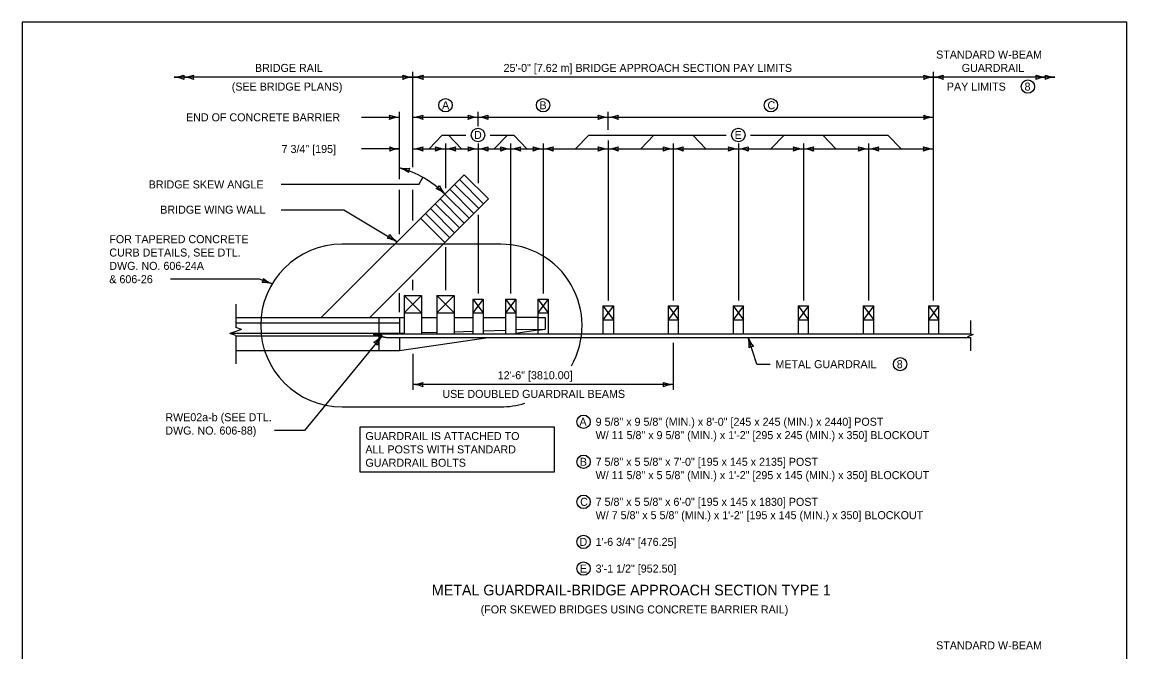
# Model space of a CAD drawing. Extents: x 49991.4 to 50021, y 49987.6 to 50011.4.
# Drawn here: x 50000.34 to 50008.61, y 50006.54 to 50011.26 of the extents above; entities that cross this region are included whole.
import ezdxf

# ---------------------------------------------------------------- set-up
doc = ezdxf.new("R2010")
doc.units = 0
for name, color, linetype in [('Level 1', 7, 'Continuous'), ('Level 2', 7, 'Continuous'), ('Level 3', 7, 'Continuous'), ('Level 4', 7, 'Continuous'), ('Level 6', 7, 'Continuous')]:
    doc.layers.add(name, color=color, linetype=linetype)

msp = doc.modelspace()

# ---------------------------------------------------------------- linework, layer by layer
at = {"layer": 'Level 1'}
for p, q in [((50002.5778, 50009.048), (50003.649, 50010.1194)), ((50003.758, 50009.8652), (50003.5764, 50010.0467)), ((50003.7943, 50009.9015), (50003.6127, 50010.0831)), ((50003.8306, 50009.9378), (50003.649, 50010.1194)), ((50003.6853, 50009.7925), (50003.5037, 50009.9741)), ((50003.7216, 50009.8288), (50003.54, 50010.0104)), ((50002.9409, 50009.048), (50003.8306, 50009.9378)), ((50003.6127, 50009.7199), (50003.4311, 50009.9014)), ((50003.649, 50009.7562), (50003.4674, 50009.9378)), ((50003.54, 50009.6472), (50003.3584, 50009.8288)), ((50003.5764, 50009.6835), (50003.3948, 50009.8651)), ((50003.5037, 50009.6109), (50003.3221, 50009.7925)), ((50003.1995, 50009.2139), (50003.3296, 50009.2139)), ((50003.1995, 50009.2139), (50003.3296, 50009.0838)), ((50003.3296, 50009.2139), (50003.1995, 50009.0838)), ((50003.1995, 50009.2139), (50003.1995, 50008.9278)), ((50003.3296, 50009.2139), (50003.3296, 50008.9278)), ((50003.4434, 50009.2139), (50003.5734, 50009.2139)), ((50003.4434, 50009.2139), (50003.5734, 50009.0838)), ((50003.5734, 50009.2139), (50003.4434, 50009.0838)), ((50003.4434, 50009.2139), (50003.4434, 50008.9278)), ((50003.5734, 50009.2139), (50003.5734, 50008.9278)), ((50003.7132, 50009.1878), (50003.7912, 50009.1878)), ((50003.7912, 50009.1878), (50003.7132, 50009.0838)), ((50003.7132, 50009.1878), (50003.7912, 50009.0838)), ((50003.7132, 50009.1878), (50003.7132, 50008.9278)), ((50003.7912, 50009.1878), (50003.7912, 50008.9278)), ((50003.957, 50009.1878), (50004.0351, 50009.1878)), ((50004.0351, 50009.1878), (50003.957, 50009.0838)), ((50003.957, 50009.1878), (50004.0351, 50009.0838)), ((50003.957, 50009.1878), (50003.957, 50008.9278)), ((50004.0351, 50009.1878), (50004.0351, 50008.9278)), ((50004.2009, 50009.1878), (50004.2789, 50009.1878)), ((50004.2789, 50009.1878), (50004.2009, 50009.0838)), ((50004.2009, 50009.1878), (50004.2789, 50009.0838)), ((50004.2009, 50009.1878), (50004.2009, 50008.9278)), ((50004.2789, 50009.1878), (50004.2789, 50008.9278)), ((50004.6885, 50009.1358), (50004.7666, 50009.1358)), ((50004.7666, 50009.1358), (50004.6885, 50009.0318)), ((50004.6885, 50009.1358), (50004.7666, 50009.0318)), ((50004.6885, 50009.1358), (50004.6885, 50008.9278)), ((50004.7666, 50009.1358), (50004.7666, 50008.9278)), ((50005.1762, 50009.1358), (50005.2542, 50009.1358)), ((50005.2542, 50009.1358), (50005.1762, 50009.0318)), ((50005.1762, 50009.1358), (50005.2542, 50009.0318)), ((50005.1762, 50009.1358), (50005.1762, 50008.9278)), ((50005.2542, 50008.9278), (50005.2542, 50009.1358)), ((50005.6639, 50009.1358), (50005.7419, 50009.1358)), ((50005.7419, 50009.1358), (50005.6639, 50009.0318)), ((50005.6639, 50009.1358), (50005.7419, 50009.0318)), ((50005.6639, 50009.1358), (50005.6639, 50008.9278)), ((50005.7419, 50008.9278), (50005.7419, 50009.1358)), ((50006.1515, 50009.1358), (50006.2295, 50009.1358)), ((50006.2295, 50009.1358), (50006.1515, 50009.0318)), ((50006.1515, 50009.1358), (50006.2295, 50009.0318)), ((50006.1515, 50009.1358), (50006.1515, 50008.9278)), ((50006.2295, 50008.9278), (50006.2295, 50009.1358)), ((50006.6392, 50009.1358), (50006.7172, 50009.1358)), ((50006.7172, 50009.1358), (50006.6392, 50009.0318)), ((50006.6392, 50009.1358), (50006.7172, 50009.0318)), ((50006.6392, 50009.1358), (50006.6392, 50008.9278)), ((50006.7172, 50008.9278), (50006.7172, 50009.1358)), ((50007.1268, 50009.1358), (50007.2048, 50009.1358)), ((50007.2048, 50009.1358), (50007.1268, 50009.0318)), ((50007.1268, 50009.1358), (50007.2048, 50009.0318)), ((50007.1268, 50009.1358), (50007.1268, 50008.9278)), ((50007.2048, 50008.9278), (50007.2048, 50009.1358)), ((50003.1995, 50009.0838), (50003.3296, 50009.0838)), ((50003.4434, 50009.0838), (50003.5734, 50009.0838)), ((50003.7132, 50009.0838), (50003.7912, 50009.0838)), ((50003.957, 50009.0838), (50004.0351, 50009.0838)), ((50004.2009, 50009.0838), (50004.2789, 50009.0838)), ((50001.9368, 50009.048), (50003.1995, 50009.048)), ((50001.9368, 50009.009), (50003.1638, 50009.009)), ((50003.0078, 50009.048), (50003.0078, 50008.9278)), ((50003.1638, 50009.048), (50003.1638, 50008.9278)), ((50003.3296, 50009.048), (50003.4434, 50009.048)), ((50003.5734, 50009.048), (50003.7132, 50009.048)), ((50003.7912, 50009.048), (50003.957, 50009.048)), ((50004.2009, 50009.048), (50004.0351, 50009.048)), ((50004.6885, 50009.0318), (50004.7666, 50009.0318)), ((50005.1762, 50009.0318), (50005.2542, 50009.0318)), ((50005.6639, 50009.0318), (50005.7419, 50009.0318)), ((50006.1515, 50009.0318), (50006.2295, 50009.0318)), ((50006.6392, 50009.0318), (50006.7172, 50009.0318)), ((50007.1268, 50009.0318), (50007.2048, 50009.0318)), ((50001.9002, 50008.931), (50003.1638, 50008.931)), ((50001.9368, 50008.9125), (50003.0331, 50008.9125)), ((50002.9688, 50008.9278), (50002.9688, 50008.9181)), ((50002.9688, 50008.9278), (50007.4416, 50008.9278)), ((50003.003, 50008.9181), (50002.9688, 50008.9181)), ((50003.0078, 50008.9178), (50003.0078, 50008.801)), ((50003.0635, 50008.8991), (50007.4416, 50008.8991)), ((50003.1638, 50008.931), (50003.1995, 50008.932)), ((50003.1638, 50008.801), (50003.8293, 50008.8991)), ((50003.1638, 50008.8991), (50003.1638, 50008.801)), ((50003.3296, 50008.9357), (50003.4434, 50008.939)), ((50003.5734, 50008.9427), (50003.7132, 50008.9466)), ((50003.7912, 50008.9488), (50003.957, 50008.9536)), ((50004.2009, 50008.9605), (50004.0351, 50008.9558)), ((50004.2009, 50008.9539), (50004.0351, 50008.9295)), ((50001.9368, 50008.801), (50003.0054, 50008.801)), ((50003.0054, 50008.801), (50003.1638, 50008.801))]:
    msp.add_line(p, q, dxfattribs=at)
msp.add_lwpolyline([(50008.6146, 50011.2628), (50000.3356, 50011.2628), (50000.3356, 50000.0624), (50008.6146, 50000.0624)], close=True, dxfattribs=at)
msp.add_spline([(50003.0635, 50008.8991), (50003.0546, 50008.899), (50003.0454, 50008.9011), (50003.0394, 50008.9052), (50003.0343, 50008.9111), (50003.0303, 50008.9151), (50003.0212, 50008.9171), (50003.003, 50008.9181)], degree=3, dxfattribs=at)
at = {"layer": 'Level 2'}
msp.add_lwpolyline([(50002.8683, 50008.2307), (50004.3234, 50008.2307), (50004.3234, 50007.8907), (50002.8683, 50007.8907)], close=True, dxfattribs=at)
for centre, radius in [((50007.8724, 50010.7794), 0.05), ((50003.5084, 50010.6398), 0.0504), ((50004.2399, 50010.6398), 0.0504), ((50005.9467, 50010.6398), 0.0504), ((50003.7522, 50010.4167), 0.0504), ((50005.703, 50010.4167), 0.0504), ((50006.9148, 50008.6994), 0.05), ((50004.543, 50008.2679), 0.0504), ((50004.543, 50007.9679), 0.0504), ((50004.543, 50007.6679), 0.0504), ((50004.543, 50007.3679), 0.0504), ((50004.543, 50007.1679), 0.0504)]:
    msp.add_circle(centre, radius, dxfattribs=at)
at = {"layer": 'Level 3'}
for p, q in [((50003.2646, 50010.1758), (50003.2644, 50010.8894)), ((50007.1658, 50009.1758), (50007.1658, 50010.8894)), ((50003.2644, 50010.8494), (50001.4745, 50010.8494)), ((50007.1658, 50010.8494), (50003.2644, 50010.8494)), ((50008.0756, 50010.8494), (50007.1658, 50010.8494)), ((50002.8786, 50010.5494), (50003.1638, 50010.5494)), ((50003.1638, 50010.0863), (50003.1638, 50010.5894)), ((50003.2645, 50010.5494), (50003.7522, 50010.5494)), ((50003.7522, 50010.4818), (50003.7522, 50010.5894)), ((50003.7522, 50010.5494), (50004.7276, 50010.5494)), ((50004.7276, 50010.4567), (50004.7276, 50010.5894)), ((50004.7276, 50010.5494), (50007.1658, 50010.5494)), ((50003.4838, 50010.4167), (50003.3856, 50010.3121)), ((50003.4838, 50010.4167), (50003.6618, 50010.4167)), ((50003.5312, 50010.4167), (50003.6294, 50010.3121)), ((50003.8427, 50010.4167), (50004.0194, 50010.4167)), ((50003.972, 50010.4167), (50003.8738, 50010.3121)), ((50004.0194, 50010.4167), (50004.1176, 50010.3121)), ((50004.582, 50010.4166), (50004.4838, 50010.312)), ((50004.582, 50010.4167), (50005.6126, 50010.4167)), ((50004.7276, 50010.3767), (50004.7276, 50009.1758)), ((50005.0697, 50010.4166), (50004.9715, 50010.312)), ((50005.3609, 50010.4166), (50005.4591, 50010.312)), ((50005.7934, 50010.4167), (50006.8239, 50010.4167)), ((50006.0452, 50010.4166), (50005.9468, 50010.312)), ((50006.3363, 50010.4166), (50006.4345, 50010.312)), ((50006.8239, 50010.4167), (50006.9222, 50010.312)), ((50003.1638, 50010.312), (50002.8786, 50010.312)), ((50003.2645, 50010.312), (50003.5084, 50010.312)), ((50003.5084, 50010.352), (50003.5084, 50010.0188)), ((50003.5084, 50010.312), (50003.7522, 50010.312)), ((50003.7522, 50010.352), (50003.7522, 50010.0561)), ((50003.7522, 50010.312), (50003.9961, 50010.312)), ((50003.9961, 50010.352), (50003.9961, 50009.2278)), ((50003.9961, 50010.312), (50004.2399, 50010.312)), ((50004.2399, 50010.352), (50004.2399, 50009.2278)), ((50004.2399, 50010.312), (50004.7276, 50010.312)), ((50004.7276, 50010.312), (50005.2153, 50010.312)), ((50005.2153, 50010.352), (50005.2153, 50009.1758)), ((50005.2153, 50010.312), (50005.703, 50010.312)), ((50005.703, 50010.352), (50005.703, 50009.1758)), ((50005.703, 50010.312), (50006.1907, 50010.312)), ((50006.1907, 50010.352), (50006.1907, 50009.1758)), ((50006.1907, 50010.312), (50006.6784, 50010.312)), ((50006.6784, 50010.352), (50006.6784, 50009.1758)), ((50006.6784, 50010.312), (50007.1658, 50010.312)), ((50003.3094, 50010.0463), (50002.2766, 50010.0463)), ((50003.3094, 50010.0463), (50003.3391, 50010.0989)), ((50003.1638, 50009.6741), (50003.1638, 50010.0063)), ((50003.2646, 50009.7749), (50003.2646, 50010.0063)), ((50002.2766, 50009.8572), (50002.7469, 50009.8572)), ((50002.7469, 50009.8572), (50003.1465, 50009.6168)), ((50003.7522, 50009.8194), (50003.7522, 50009.2278)), ((50003.5084, 50009.5756), (50003.5084, 50009.2539)), ((50002.1147, 50009.3361), (50001.4479, 50009.3361)), ((50002.209, 50009.3005), (50002.1147, 50009.3361)), ((50003.2646, 50009.2539), (50003.2646, 50009.3317)), ((50003.1638, 50009.088), (50003.1638, 50009.2309)), ((50003.0331, 50008.9125), (50002.4529, 50008.2019)), ((50005.841, 50008.6994), (50005.7759, 50008.8991)), ((50005.2154, 50008.8591), (50005.2154, 50008.5067)), ((50003.2646, 50008.7758), (50003.2646, 50008.5067)), ((50005.841, 50008.6994), (50005.9408, 50008.6994)), ((50005.2154, 50008.5467), (50003.2646, 50008.5467)), ((50002.4529, 50008.2019), (50002.2274, 50008.2019))]:
    msp.add_line(p, q, dxfattribs=at)
for centre, radius, start, end in [((50001.4633, 50011.0764), 0.2273, 272.82731, 292.07716), ((50001.4656, 50010.6327), 0.2168, 67.45601, 87.63952), ((50001.5996, 50010.8494), 0.0534, 162.13882, 197.86118), ((50001.5349, 50011.0764), 0.2273, 272.82731, 292.07716), ((50001.5372, 50010.6327), 0.2168, 67.45601, 87.63952), ((50001.6712, 50010.8494), 0.0534, 162.13882, 197.86118), ((50003.2736, 50011.0715), 0.2223, 247.45601, 267.63952), ((50003.1362, 50010.8494), 0.0548, 342.13882, 17.86118), ((50003.2759, 50010.6167), 0.233, 92.82731, 112.07716), ((50003.2529, 50011.0821), 0.233, 272.82731, 292.07716), ((50003.2552, 50010.6273), 0.2223, 67.45601, 87.63952), ((50003.3926, 50010.8494), 0.0548, 162.13882, 197.86118), ((50007.1745, 50011.0605), 0.2113, 247.45601, 267.63952), ((50007.044, 50010.8494), 0.0521, 342.13882, 17.86118), ((50007.1767, 50010.6283), 0.2214, 92.82731, 112.07716), ((50007.1549, 50011.0706), 0.2214, 272.82731, 292.07716), ((50007.1571, 50010.6383), 0.2113, 67.45601, 87.63952), ((50007.2876, 50010.8494), 0.0521, 162.13882, 197.86118), ((50008.0145, 50011.0605), 0.2113, 247.45601, 267.63952), ((50007.884, 50010.8494), 0.0521, 342.13882, 17.86118), ((50008.0167, 50010.6283), 0.2214, 92.82731, 112.07716), ((50008.0843, 50011.0605), 0.2113, 247.45601, 267.63952), ((50007.9538, 50010.8494), 0.0521, 342.13882, 17.86118), ((50008.0865, 50010.6283), 0.2214, 92.82731, 112.07716), ((50003.1727, 50010.766), 0.2168, 247.45601, 267.63952), ((50003.0387, 50010.5494), 0.0534, 342.13882, 17.86118), ((50003.175, 50010.3224), 0.2273, 92.82731, 112.07716), ((50003.2533, 50010.7763), 0.2273, 272.82731, 292.07716), ((50003.2556, 50010.3327), 0.2168, 67.45601, 87.63952), ((50003.3896, 50010.5494), 0.0534, 162.13882, 197.86118), ((50003.7612, 50010.766), 0.2168, 247.45601, 267.63952), ((50003.6272, 50010.5494), 0.0534, 342.13882, 17.86118), ((50003.7634, 50010.3224), 0.2273, 92.82731, 112.07716), ((50003.741, 50010.7763), 0.2273, 272.82731, 292.07716), ((50003.7433, 50010.3327), 0.2168, 67.45601, 87.63952), ((50003.8773, 50010.5494), 0.0534, 162.13882, 197.86118), ((50004.7365, 50010.766), 0.2168, 247.45601, 267.63952), ((50004.6025, 50010.5494), 0.0534, 342.13882, 17.86118), ((50004.7388, 50010.3224), 0.2273, 92.82731, 112.07716), ((50004.7164, 50010.7763), 0.2273, 272.82731, 292.07716), ((50004.7187, 50010.3327), 0.2168, 67.45601, 87.63952), ((50004.8527, 50010.5494), 0.0534, 162.13882, 197.86118), ((50007.1745, 50010.7605), 0.2113, 247.45601, 267.63952), ((50007.044, 50010.5494), 0.0521, 342.13882, 17.86118), ((50007.1767, 50010.3282), 0.2214, 92.82731, 112.07716), ((50003.1725, 50010.5231), 0.2113, 247.45601, 267.63952), ((50003.0419, 50010.312), 0.0521, 342.13882, 17.86118), ((50003.1747, 50010.0909), 0.2214, 92.82731, 112.07716), ((50003.2533, 50010.539), 0.2273, 272.82731, 292.07716), ((50003.2556, 50010.0954), 0.2168, 67.45601, 87.63952), ((50003.3896, 50010.312), 0.0534, 162.13882, 197.86118), ((50003.5173, 50010.5287), 0.2168, 247.45601, 267.63952), ((50003.3833, 50010.312), 0.0534, 342.13882, 17.86118), ((50003.5196, 50010.085), 0.2273, 92.82731, 112.07716), ((50003.4972, 50010.539), 0.2273, 272.82731, 292.07716), ((50003.4995, 50010.0954), 0.2168, 67.45601, 87.63952), ((50003.6335, 50010.312), 0.0534, 162.13882, 197.86118), ((50003.7612, 50010.5287), 0.2168, 247.45601, 267.63952), ((50003.6272, 50010.312), 0.0534, 342.13882, 17.86118), ((50003.7634, 50010.085), 0.2273, 92.82731, 112.07716), ((50003.741, 50010.539), 0.2273, 272.82731, 292.07716), ((50003.7433, 50010.0954), 0.2168, 67.45601, 87.63952), ((50003.8773, 50010.312), 0.0534, 162.13882, 197.86118), ((50004.005, 50010.5287), 0.2168, 247.45601, 267.63952), ((50003.871, 50010.312), 0.0534, 342.13882, 17.86118), ((50004.0073, 50010.085), 0.2273, 92.82731, 112.07716), ((50003.9849, 50010.539), 0.2273, 272.82731, 292.07716), ((50003.9872, 50010.0954), 0.2168, 67.45601, 87.63952), ((50004.1211, 50010.312), 0.0534, 162.13882, 197.86118), ((50004.2489, 50010.5287), 0.2168, 247.45601, 267.63952), ((50004.1149, 50010.312), 0.0534, 342.13882, 17.86118), ((50004.2511, 50010.085), 0.2273, 92.82731, 112.07716), ((50004.2287, 50010.539), 0.2273, 272.82731, 292.07716), ((50004.231, 50010.0954), 0.2168, 67.45601, 87.63952), ((50004.365, 50010.312), 0.0534, 162.13882, 197.86118), ((50004.7365, 50010.5287), 0.2168, 247.45601, 267.63952), ((50004.6026, 50010.312), 0.0534, 342.13882, 17.86118), ((50004.7388, 50010.085), 0.2273, 92.82731, 112.07716), ((50004.7164, 50010.539), 0.2273, 272.82731, 292.07716), ((50004.7187, 50010.0954), 0.2168, 67.45601, 87.63952), ((50004.8527, 50010.312), 0.0534, 162.13882, 197.86118), ((50005.2242, 50010.5287), 0.2168, 247.45601, 267.63952), ((50005.0902, 50010.312), 0.0534, 342.13882, 17.86118), ((50005.2265, 50010.085), 0.2273, 92.82731, 112.07716), ((50005.2041, 50010.539), 0.2273, 272.82731, 292.07716), ((50005.2064, 50010.0954), 0.2168, 67.45601, 87.63952), ((50005.3404, 50010.312), 0.0534, 162.13882, 197.86118), ((50005.7119, 50010.5287), 0.2168, 247.45601, 267.63952), ((50005.5779, 50010.312), 0.0534, 342.13882, 17.86118), ((50005.7142, 50010.085), 0.2273, 92.82731, 112.07716), ((50005.6918, 50010.539), 0.2273, 272.82731, 292.07716), ((50005.6941, 50010.0954), 0.2168, 67.45601, 87.63952), ((50005.828, 50010.312), 0.0534, 162.13882, 197.86118), ((50006.1996, 50010.5287), 0.2168, 247.45601, 267.63952), ((50006.0656, 50010.312), 0.0534, 342.13882, 17.86118), ((50006.2019, 50010.085), 0.2273, 92.82731, 112.07716), ((50006.1795, 50010.539), 0.2273, 272.82731, 292.07716), ((50006.1817, 50010.0954), 0.2168, 67.45601, 87.63952), ((50006.3157, 50010.312), 0.0534, 162.13882, 197.86118), ((50006.6873, 50010.5287), 0.2168, 247.45601, 267.63952), ((50006.5533, 50010.312), 0.0534, 342.13882, 17.86118), ((50006.6896, 50010.085), 0.2273, 92.82731, 112.07716), ((50006.6672, 50010.539), 0.2273, 272.82731, 292.07716), ((50006.6694, 50010.0954), 0.2168, 67.45601, 87.63952), ((50006.8034, 50010.312), 0.0534, 162.13882, 197.86118), ((50007.1747, 50010.5287), 0.2168, 247.45601, 267.63952), ((50007.0407, 50010.312), 0.0534, 342.13882, 17.86118), ((50007.177, 50010.085), 0.2273, 92.82731, 112.07716), ((50002.9623, 50009.4309), 0.767, 45.09469, 74.7701), ((50003.0982, 50009.9642), 0.2168, 52.22611, 72.40962), ((50003.2126, 50010.3928), 0.2273, 257.59741, 276.84726), ((50003.2844, 50010.138), 0.0534, 146.90892, 182.63128), ((50003.4151, 50010.0624), 0.0534, 297.23351, 332.95587), ((50003.3514, 50009.8054), 0.2273, 47.922, 67.17185), ((50003.663, 50010.1212), 0.2168, 202.5507, 222.73421), ((50003.0366, 50009.6829), 0.0548, 311.10792, 346.83028), ((50003.0364, 50009.4115), 0.233, 61.79641, 81.04626), ((50003.2689, 50009.8025), 0.2223, 216.42511, 236.60862), ((50002.0921, 50009.3447), 0.0534, 321.39597, 357.11833), ((50002.1392, 50009.0844), 0.2271, 72.08446, 91.33431), ((50002.2941, 50009.4998), 0.2167, 226.71316, 246.89667), ((50002.8668, 50009.0601), 0.2223, 298.22822, 318.41173), ((50003.2206, 50008.7743), 0.233, 143.59952, 162.84937), ((50005.5619, 50008.839), 0.2223, 355.50296, 15.68647), ((50005.9936, 50008.9821), 0.233, 200.87426, 220.12411), ((50002.952, 50008.8132), 0.0548, 32.91103, 68.63339), ((50005.8157, 50008.7772), 0.0548, 90.18577, 125.90813), ((50003.2534, 50008.7737), 0.2273, 272.82731, 292.07716), ((50003.3897, 50008.5467), 0.0534, 162.13882, 197.86118), ((50005.2243, 50008.7634), 0.2168, 247.45601, 267.63952), ((50005.0903, 50008.5467), 0.0534, 342.13882, 17.86118), ((50003.2557, 50008.3301), 0.2168, 67.45601, 87.63952), ((50005.2266, 50008.3198), 0.2273, 92.82731, 112.07716)]:
    msp.add_arc(centre, radius, start, end, dxfattribs=at)
at = {"layer": 'Level 4'}
for p, q in [((50002.733, 50009.5984), (50002.733, 50009.5986)), ((50003.9226, 50009.5984), (50002.733, 50009.5984)), ((50004.2009, 50009.048), (50004.2561, 50009.048)), ((50004.2561, 50009.048), (50004.2561, 50008.9621)), ((50004.2009, 50008.9539), (50004.2561, 50008.9621)), ((50004.2009, 50008.9605), (50004.2561, 50008.9621)), ((50002.733, 50008.3794), (50002.733, 50008.3792)), ((50002.733, 50008.3792), (50003.9226, 50008.3792))]:
    msp.add_line(p, q, dxfattribs=at)
msp.add_arc((50002.733, 50008.989), 0.6096, 90, 270, dxfattribs=at)
for centre, major_axis, ratio, start_param, end_param in [((50003.9225, 50008.9888), (0, -0.6097), 0.999822, 1.052352, 3.141593), ((50003.9225, 50009.2381), (0, -0.8588), 0.840597, 0, 0.253504)]:
    msp.add_ellipse(centre, major_axis=major_axis, ratio=ratio, start_param=start_param, end_param=end_param, dxfattribs=at)
at = {"layer": 'Level 6'}
for p, q in [((50001.9368, 50009.148), (50001.9368, 50008.9748)), ((50001.9802, 50008.9594), (50001.9368, 50008.9748)), ((50007.4416, 50009.0278), (50007.4416, 50008.9266)), ((50001.9368, 50008.9131), (50001.8932, 50008.9286)), ((50001.9368, 50008.944), (50001.8934, 50008.9286)), ((50001.9802, 50008.9594), (50001.9368, 50008.944)), ((50001.9368, 50008.9131), (50001.9368, 50008.701)), ((50007.4633, 50008.9207), (50007.4199, 50008.9053)), ((50007.4199, 50008.9053), (50007.4416, 50008.8998)), ((50007.4416, 50008.9266), (50007.4633, 50008.9207)), ((50007.4416, 50008.8998), (50007.4416, 50008.7991))]:
    msp.add_line(p, q, dxfattribs=at)

# ---------------------------------------------------------------- texts
at = {"layer": 'Level 2'}
for s, height, p in [('STANDARD W-BEAM', 0.06, (50007.185, 50010.9894)), ('BRIDGE RAIL', 0.06, (50002.0806, 50010.8894)), ('25\'-0" [7.62 m] BRIDGE APPROACH SECTION PAY LIMITS', 0.06, (50003.9435, 50010.8894)), ('GUARDRAIL', 0.06, (50007.377, 50010.8894)), ('(SEE BRIDGE PLANS)', 0.06, (50001.9068, 50010.7494)), ('PAY LIMITS', 0.06, (50007.2655, 50010.7494)), ('8', 0.06, (50007.8475, 50010.7495)), ('A', 0.06, (50003.4826, 50010.6098)), ('B', 0.06, (50004.2122, 50010.6098)), ('C', 0.06, (50005.9212, 50010.6098)), ('END OF CONCRETE BARRIER', 0.06, (50001.564, 50010.5194)), ('D', 0.06, (50003.7219, 50010.3867)), ('E', 0.06, (50005.675, 50010.3867)), ('7 3/4" [195]', 0.06, (50002.2802, 50010.282)), ('BRIDGE SKEW ANGLE', 0.06, (50001.2844, 50010.0163)), ('BRIDGE WING WALL', 0.06, (50001.3707, 50009.8272)), ('FOR TAPERED CONCRETE', 0.06, (50000.9892, 50009.6061)), ('CURB DETAILS, SEE DTL. ', 0.06, (50000.9892, 50009.5061)), ('DWG. NO. 606-24A ', 0.06, (50000.9892, 50009.4061)), ('& 606-26', 0.06, (50000.9892, 50009.3061)), ('METAL GUARDRAIL', 0.06, (50005.9808, 50008.6694)), ('8', 0.06, (50006.8898, 50008.6694)), ('12\'-6" [3810.00]', 0.06, (50003.8997, 50008.5867)), ('USE DOUBLED GUARDRAIL BEAMS', 0.06, (50003.4851, 50008.4467)), ('RWE02a-b (SEE DTL.', 0.06, (50001.4089, 50008.2719)), ('DWG. NO. 606-88)', 0.06, (50001.4089, 50008.1719)), ('A', 0.06, (50004.5125, 50008.2379)), ('9 5/8" x 9 5/8" (MIN.) x 8\'-0" [245 x 245 (MIN.) x 2440] POST', 0.06, (50004.6334, 50008.2379)), ('GUARDRAIL IS ATTACHED TO ', 0.06, (50002.9083, 50008.1308)), ('W/ 11 5/8" x 9 5/8" (MIN.) x 1\'-2" [295 x 245 (MIN.) x 350] BLOCKOUT', 0.06, (50004.6334, 50008.1379)), ('ALL POSTS WITH STANDARD', 0.06, (50002.9083, 50008.0308)), ('GUARDRAIL BOLTS', 0.06, (50002.9083, 50007.9308)), ('B', 0.06, (50004.5153, 50007.9379)), ('7 5/8" x 5 5/8" x 7\'-0" [195 x 145 x 2135] POST', 0.06, (50004.6334, 50007.9379)), ('W/ 11 5/8" x 5 5/8" (MIN.) x 1\'-2" [295 x 145 (MIN.) x 350] BLOCKOUT', 0.06, (50004.6334, 50007.8379)), ('C', 0.06, (50004.5175, 50007.6379)), ('7 5/8" x 5 5/8" x 6\'-0" [195 x 145 x 1830] POST', 0.06, (50004.6334, 50007.6379)), ('W/ 7 5/8" x 5 5/8" (MIN.) x 1\'-2" [195 x 145 (MIN.) x 350] BLOCKOUT', 0.06, (50004.6334, 50007.5379)), ('D', 0.06, (50004.5127, 50007.3379)), ('1\'-6 3/4" [476.25]', 0.06, (50004.6334, 50007.3379)), ('E', 0.06, (50004.5151, 50007.1379)), ('3\'-1 1/2" [952.50]', 0.06, (50004.6334, 50007.1379)), ('METAL GUARDRAIL-BRIDGE APPROACH SECTION TYPE 1', 0.08, (50003.4058, 50006.9668)), ('(FOR SKEWED BRIDGES USING CONCRETE BARRIER RAIL)', 0.06, (50003.7721, 50006.8316)), ('STANDARD W-BEAM', 0.06, (50007.185, 50006.5622))]:
    msp.add_text(s, height=height, dxfattribs=at).set_placement(p)

doc.saveas('drawing.dxf')
